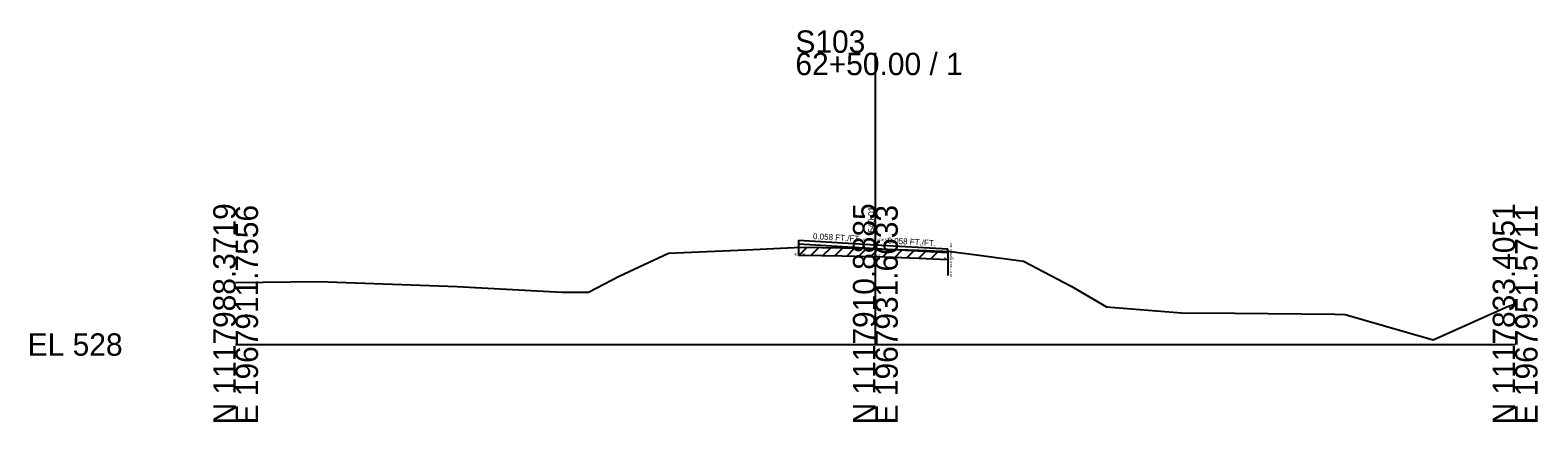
# Model space of a CAD drawing. Extents: x -26 to 163, y -10 to 24018.
# Drawn here: x -25.7 to 162.8, y 10490.3 to 10539.4 of the extents above; entities that cross this region are included whole.
import ezdxf

# ---------------------------------------------------------------- set-up
doc = ezdxf.new("R2010")
doc.units = 0
for name, color, linetype in [('RD_GPK_XS_Cell', 7, 'Continuous'), ('RD_XS_ExGround', 7, 'Continuous'), ('RD_XS_ExPaveRet', 7, 'Continuous'), ('RD_XS_Misc_Line', 7, 'Continuous'), ('RD_XS_PaveOvlay_CP', 7, 'Continuous'), ('RD_XS_TX_Elev_EX', 7, 'Continuous'), ('RD_XS_TX_ExEOP', 7, 'Continuous'), ('RD_XS_TX_Notes', 7, 'Continuous'), ('RD_XS_TX_Profile', 7, 'Continuous'), ('RD_XS_TX_Slope', 7, 'Continuous')]:
    doc.layers.add(name, color=color, linetype=linetype)

msp = doc.modelspace()

# ---------------------------------------------------------------- linework, layer by layer
at = {"layer": 'RD_GPK_XS_Cell'}
for p, q in [((80, 10500), (80, 10536.55)), ((0, 10500), (80, 10500)), ((80, 10500), (160, 10500))]:
    msp.add_line(p, q, dxfattribs=at)
at = {"layer": 'RD_XS_ExGround'}
msp.add_lwpolyline([(0, 10507.79), (10.35, 10507.91), (27.7, 10507.26), (40.79, 10506.57), (44.11, 10506.55), (47.95, 10508.58), (54.12, 10511.43), (64.71, 10511.91), (70.71, 10512.18), (75.83, 10512.1), (79.06, 10512.04), (80, 10512.01), (85.44, 10511.81), (89.39, 10511.64), (92.63, 10511.25), (98.51, 10510.43), (104.47, 10507.3), (108.91, 10504.71), (118.26, 10503.99), (124.93, 10503.94), (137.45, 10503.8), (138.75, 10503.76), (143.66, 10502.34), (149.73, 10500.58), (158.98, 10504.73), (160, 10505.09)], dxfattribs=at)
at = {"layer": 'RD_XS_ExPaveRet'}
for p, q in [((70.43, 10511.17), (71.43, 10512.17)), ((70.43, 10511.17), (70.43, 10512.17)), ((70.43, 10511.17), (70.71, 10511.18)), ((70.71, 10511.18), (75.83, 10511.1)), ((71.93, 10511.16), (72.91, 10512.15)), ((73.43, 10511.14), (74.41, 10512.12)), ((74.93, 10511.11), (75.91, 10512.1)), ((75.83, 10511.1), (79.06, 10511.04)), ((76.43, 10511.09), (77.41, 10512.07)), ((77.93, 10511.06), (78.91, 10512.04)), ((79.06, 10511.04), (80, 10511.01)), ((79.43, 10511.03), (80.4, 10511.99)), ((80, 10511.01), (85.44, 10510.81)), ((80.93, 10510.97), (81.9, 10511.94)), ((82.43, 10510.92), (83.4, 10511.89)), ((83.93, 10510.87), (84.9, 10511.83)), ((85.43, 10510.81), (86.39, 10511.77)), ((85.44, 10510.81), (89.08, 10510.66)), ((86.93, 10510.75), (87.89, 10511.71)), ((89.08, 10511.66), (89.08, 10510.66))]:
    msp.add_line(p, q, dxfattribs=at)
at = {"layer": 'RD_XS_Misc_Line'}
msp.add_line((89.08, 10511.66), (89.08, 10508.66), dxfattribs=at)
at = {"layer": 'RD_XS_PaveOvlay_CP'}
for p, q in [((70.43, 10513.06), (80, 10512.5)), ((70.43, 10512.17), (70.43, 10513.06)), ((80, 10512.01), (70.43, 10512.56)), ((80, 10512.5), (89.08, 10511.98)), ((89.08, 10511.48), (80, 10512.01)), ((89.08, 10511.66), (89.08, 10511.98))]:
    msp.add_line(p, q, dxfattribs=at)

# ---------------------------------------------------------------- texts
at = {"layer": 'RD_GPK_XS_Cell'}
for s, p in [('S103', (70, 10536.55)), ('62+50.00 / 1', (70, 10533.75)), ('EL 528', (-26, 10498.6))]:
    msp.add_text(s, height=2.8, dxfattribs=at).set_placement(p)
for s, p in [('N 1117988.3719', (0, 10490)), ('E 1967911.7556', (2.8, 10490)), ('N 1117910.8885', (80, 10490)), ('E 1967931.6633', (82.8, 10490)), ('N 1117833.4051', (160, 10490)), ('E 1967951.5711', (162.8, 10490))]:
    msp.add_text(s, height=2.8, rotation=90, dxfattribs=at).set_placement(p)
at = {"layer": 'RD_XS_TX_Elev_EX'}
msp.add_text('540.01', height=0.8, rotation=90, dxfattribs=at).set_placement((79.9, 10514.01))
at = {"layer": 'RD_XS_TX_ExEOP'}
for s, p in [('EOP-L', (70.38, 10513.06)), ('EOP-R', (89.03, 10511.98))]:
    msp.add_text(s, height=0.1, rotation=270, dxfattribs=at).set_placement(p)
at = {"layer": 'RD_XS_TX_Notes'}
for s, p in [('Elev. @CL = 540.50', (78.47, 10513)), (' dE= 0.89', (69.72, 10511.17)), (' dE= 0.50', (79.29, 10511.01)), (' dE= 0.32', (88.36, 10510.66))]:
    msp.add_text(s, height=0.25, dxfattribs=at).set_placement(p)
msp.add_text(' Min. Distance @CP = -0.18', height=0.25, rotation=270, dxfattribs=at).set_placement((89.33, 10512.75))
at = {"layer": 'RD_XS_TX_Profile'}
msp.add_text('CL', height=0.25, dxfattribs=at).set_placement((79.77, 10512.5))
at = {"layer": 'RD_XS_TX_Slope'}
for p in [(72.18, 10513.21), (81.5, 10512.67)]:
    msp.add_text('0.058 FT./FT.', height=0.75, rotation=356.6806, dxfattribs=at).set_placement(p)

doc.saveas('drawing.dxf')
